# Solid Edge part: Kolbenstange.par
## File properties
Username: ahadarics
Dokumentum tartalom típus: 0
Author: ahadarics
Last saved by: ahadarics
Revision: 78
Sűrűség: 0,000 kg/m^3
Pontosság: 0,990
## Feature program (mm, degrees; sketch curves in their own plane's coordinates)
base feature "unnamed BaseFeature 1"
sketch for "Furat_1" plane through (-10, 0, 0) normal (-1, 0, 0) x-axis (0, 1, 0)
  hole centre (0, 0) bore radius 4.188
hole "Furat_1" nominal diameter 10 finite  ThreadDepth = 17 mm
sketch for "Kihúzás_1" plane through (43.5, 0, 0) normal (1, 0, 0) x-axis (0, -1, 0)
  circle centre (0, 0) radius 25
extrude "Kihúzás_1" add finite 16 along -normal
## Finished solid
Body 1: solid body, 13 faces, 19 edges, 8 vertices.
  Faces by surface: plane 8, cylinder 3, cone 1, torus 1
  Edges by curve: circle 9, line 6, ellipse 2, intersection 2
Bounding box of the edges (mm; curved faces can reach further): 53.500 x 50.000 x 50.000, from (-10, -25, -25) to (43.5, 25, 25).
Cylindrical faces by radius (mm): R4.188 x1, R8 x1, R25 x1
Conical faces (half-angle, radius in mm at the cone's reference point): 45 deg R4.185 x1
Toroidal faces (ring radius, tube radius in mm): R6.3 r1.7 x1
Planar faces by outward normal: +x 1, +z 1, -x 3, -z 1, oblique 2
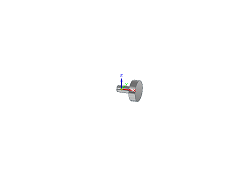
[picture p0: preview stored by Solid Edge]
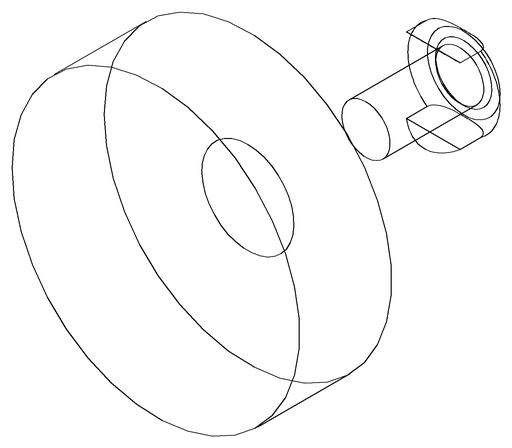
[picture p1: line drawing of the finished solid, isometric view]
